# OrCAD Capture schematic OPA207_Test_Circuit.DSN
size A; title: OPA207 Low-Power, High-Precision, Low-Noise, Rail-to-Rail; rev: 1.2; note: Datasheet: SBOS826D   EVM: N/A
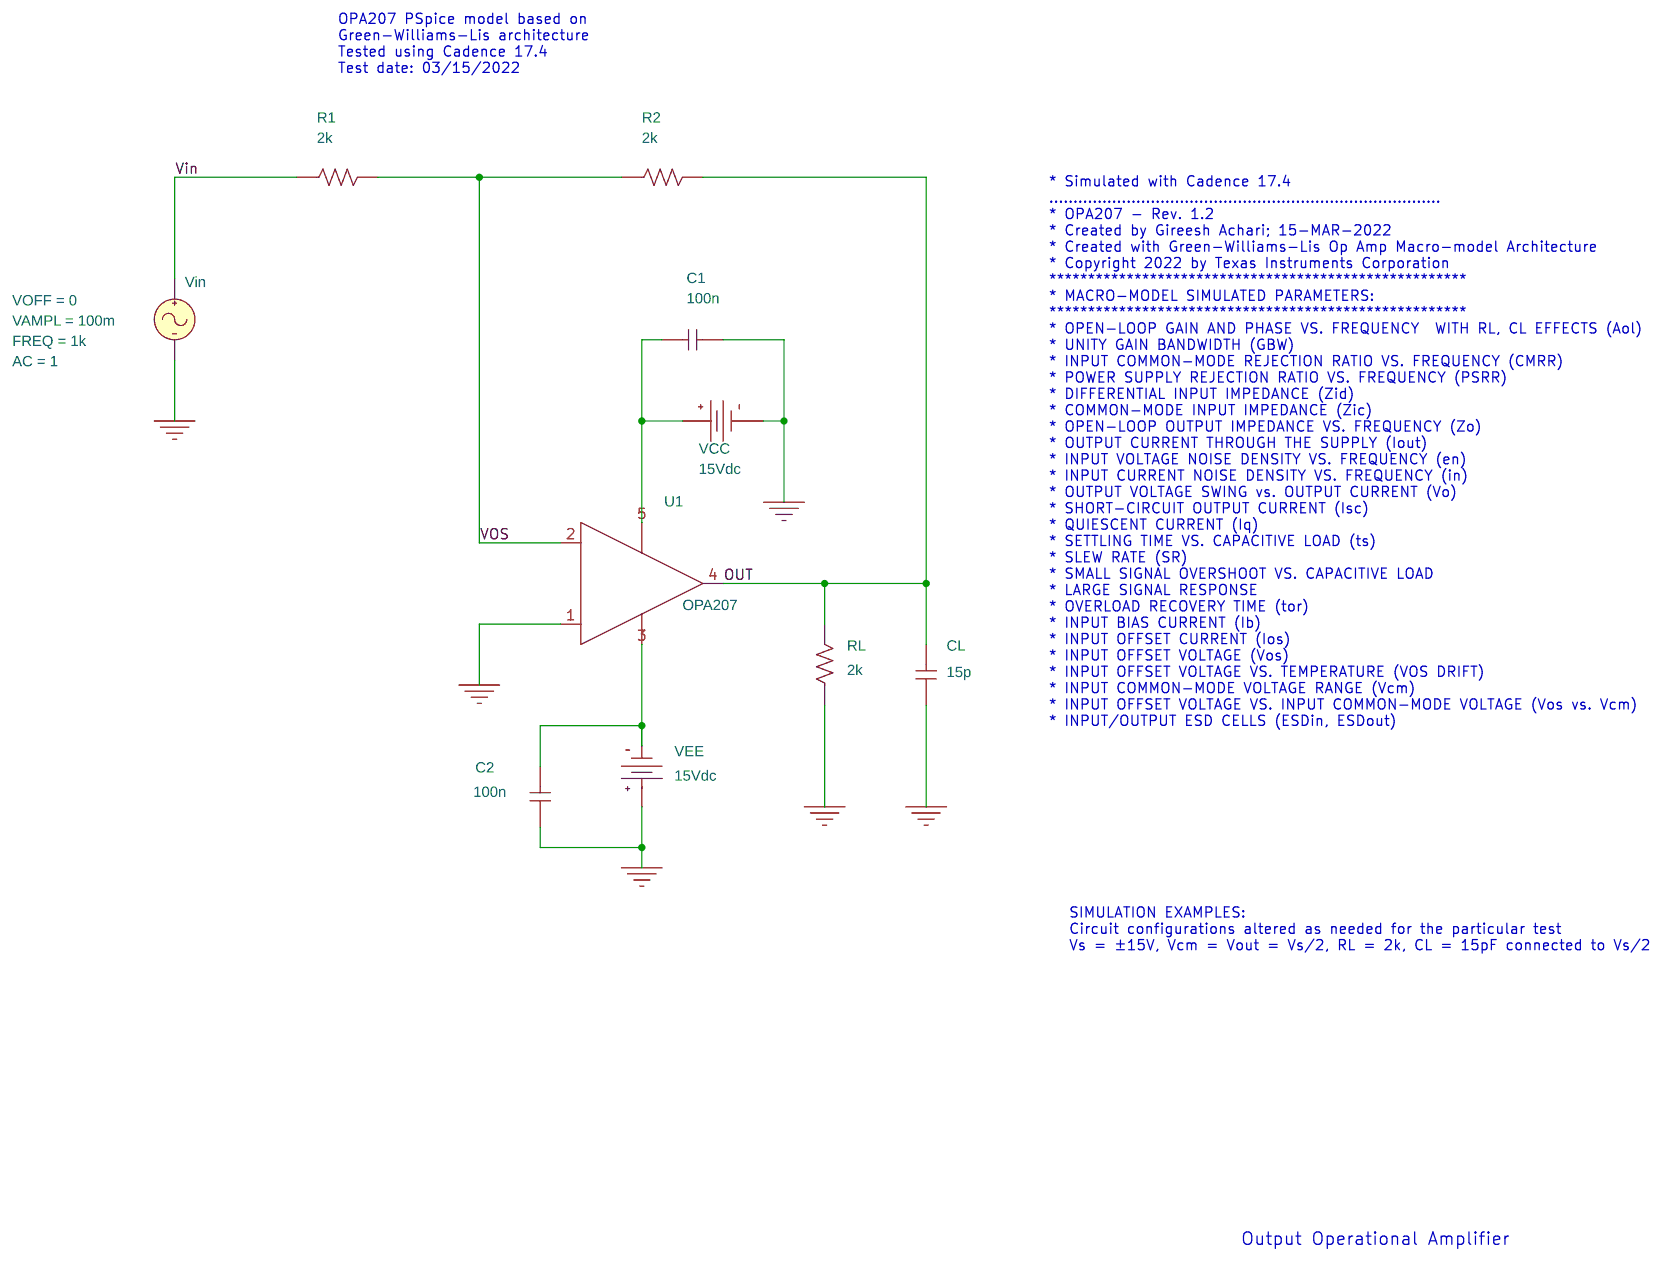
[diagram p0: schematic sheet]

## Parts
C1  100n  [cap196]
C2  100n  [cap196]
CL  15p  [cap196]
R1  2k  [AXRC05]
R2  2k  [AXRC05]
RL  2k  [AXRC05]
U1  OPA207
VCC  VDC
VEE  VDC
Vin  VSIN

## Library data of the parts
C1 C2 CL = C
R1 R2 RL = R
U1 = OPA207
VCC VEE = VDC: DC: 15Vdc
Vin = VSIN: AC: 1; FREQ: 1k; VAMPL: 100m; VOFF: 0

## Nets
Vin: R1.1 Vin.1(+)
0: C1.2 C2.1 CL.2 RL.1 U1.1(+) VCC.1(-) VEE.0(+) Vin.2(-)
OUT: CL.1 R2.2 RL.2 U1.4(OUT)
VOS: R1.2 R2.1 U1.2(-)
N27303: C1.1 U1.5(V+) VCC.0(+)
N27354: C2.2 U1.3(V-) VEE.1(-)

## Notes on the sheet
- OPA207 PSpice model based on
  Green-Williams-Lis architecture
  Tested using Cadence 17.4
  Test date: 03/15/2022
- * Simulated with Cadence 17.4
  .................................................................................
  * OPA207 - Rev. 1.2
  * Created by Gireesh Achari; 15-MAR-2022
  * Created with Green-Williams-Lis Op Amp Macro-model Architecture
  * Copyright 2022 by Texas Instruments Corporation
  ******************************************************
  * MACRO-MODEL SIMULATED PARAMETERS:
  ******************************************************
  * OPEN-LOOP GAIN AND PHASE VS. FREQUENCY  WITH RL, CL EFFECTS (Aol)
  * UNITY GAIN BANDWIDTH (GBW)
  * INPUT COMMON-MODE REJECTION RATIO VS. FREQUENCY (CMRR)
  * POWER SUPPLY REJECTION RATIO VS. FREQUENCY (PSRR)
  * DIFFERENTIAL INPUT IMPEDANCE (Zid)
  * COMMON-MODE INPUT IMPEDANCE (Zic)
  * OPEN-LOOP OUTPUT IMPEDANCE VS. FREQUENCY (Zo)
  * OUTPUT CURRENT THROUGH THE SUPPLY (Iout)
  * INPUT VOLTAGE NOISE DENSITY VS. FREQUENCY (en)
  * INPUT CURRENT NOISE DENSITY VS. FREQUENCY (in)
  * OUTPUT VOLTAGE SWING vs. OUTPUT CURRENT (Vo)
  * SHORT-CIRCUIT OUTPUT CURRENT (Isc)
  * QUIESCENT CURRENT (Iq)
  * SETTLING TIME VS. CAPACITIVE LOAD (ts)
  * SLEW RATE (SR)
  * SMALL SIGNAL OVERSHOOT VS. CAPACITIVE LOAD
  * LARGE SIGNAL RESPONSE
  * OVERLOAD RECOVERY TIME (tor)
  * INPUT BIAS CURRENT (Ib)
  * INPUT OFFSET CURRENT (Ios)
  * INPUT OFFSET VOLTAGE (Vos)
  * INPUT OFFSET VOLTAGE VS. TEMPERATURE (VOS DRIFT)
  * INPUT COMMON-MODE VOLTAGE RANGE (Vcm)
  * INPUT OFFSET VOLTAGE VS. INPUT COMMON-MODE VOLTAGE (Vos vs. Vcm)
  * INPUT/OUTPUT ESD CELLS (ESDin, ESDout)
- SIMULATION EXAMPLES:
  Circuit configurations altered as needed for the particular test
  Vs = ±15V, Vcm = Vout = Vs/2, RL = 2k, CL = 15pF connected to Vs/2
- Output Operational Amplifier
